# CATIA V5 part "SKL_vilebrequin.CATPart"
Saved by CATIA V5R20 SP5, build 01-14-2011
Part number: SKL_vilebrequin
Publications: "Point.1", "Point.3", "Droite.1", "Plan.1", "Droite.2", "Droite.3"
Bounding box of the stored display mesh (mm): x 0 to 0, y 0 to 6, z -10 to 10
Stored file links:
  F:\Catia_finish\SKL_vilebrequin.CATPart
  F:\Catia_finish\ASS_SKL.CATProduct
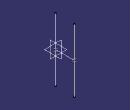
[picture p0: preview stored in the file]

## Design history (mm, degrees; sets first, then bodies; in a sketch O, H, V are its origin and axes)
Set1
  Point1: linked copy from another document
  Point2: linked copy from another document
  Plane1: linked copy from another document
Set2 "set vilebrequin"
  Point3: (0, 0, 0), relative to Point1
  Point4: (0, 0, 0), relative to Point2
  Line1: type PtPt, FirstPoint Point3, SecondPoint Point2
  Plane2: type Offset, RefPlane Plane1, Offset 0
  Line2: type Normal, RefPoint Point3, RefSkin Plane2, Start -10, End 10
  Line3: type Normal, RefPoint Point4, RefSkin Plane2, Start -10, End 10
Body1 (main body)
